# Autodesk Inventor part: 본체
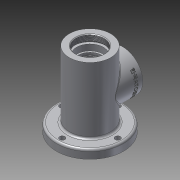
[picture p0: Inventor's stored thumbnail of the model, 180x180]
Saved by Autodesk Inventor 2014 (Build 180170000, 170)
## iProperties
Created: 2016-08
Part Number: 본체
Material: 알루미늄 6061
Document SubType Name: Modeling
Designer: USER
Density: 2.71138 g/cm^3
Appearance: 알루미늄 - 평지
Mass: 767 g
Surface Area: 622.621 cm^2
Volume: 282.882 cm^3
Author: USER
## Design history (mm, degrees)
sketch "스케치3"
  geometry: C1 r 31 at (0, 0); 1 further point
  constraints: 1 centre point, 1 coincident
  dimensions: "d14" = 62 diameter of C1
extrude "돌출1" new body sketch "스케치3" distance "d15" = 115; taper "d16" = 0 deg
node "작업 평면1"
sketch "스케치5"
  geometry: C1 r 50 at (0, 0); 1 further point
  constraints: 1 centre point, 1 coincident
  dimensions: "d19" = 100 diameter of C1
extrude "돌출2" join sketch "스케치5" distance "d20" = 13; taper "d21" = 0 deg
sketch "스케치8"
  geometry: L1 (0, 0)-(0, 115); L2 (0, 0)-(21, 0); L3 (21, 0)-(16, 14); L4 (16, 14)-(12.904, 14); L5 (12.904, 14)-(12.5, 14.7); L6 (12.5, 14.7)-(12.5, 22); L7 (12.5, 22)-(10, 22); L8 (10, 22)-(10, 24.7); L9 (10, 24.7)-(16.5, 24.7); L10 (16.5, 24.7)-(16.5, 29.7); L11 (16.5, 29.7)-(17.5, 29.7); L12 (17.5, 29.7)-(17.5, 38.946); L13 (26, 40)-(26, 78); L14 (26, 78)-(18.262, 78); L15 (17.5, 79.32)-(17.5, 89); L16 (17.5, 89)-(18.5, 89); L17 (18.5, 89)-(18.5, 90.75); L18 (18.5, 90.75)-(17.5, 90.75); L19 (17.5, 90.75)-(17.5, 94); L20 (17.5, 94)-(20, 94); L21 (20, 94)-(20, 103); L22 (20, 103)-(24, 103); L23 (24, 103)-(24, 106); L24 (24, 106)-(21, 106); L25 (21, 106)-(21, 115); L26 (31, 115)-(-31, 115) reference; L27 (26, 59)-(44.925, 59); L28 (21, 115)-(0, 115); L29 (26, 40)-(18.108, 40); L30 (18.108, 40)-(17.5, 38.946); L31 (18.262, 78)-(17.5, 79.32)
  constraints: 60 end point, 14 parallel, 9 perpendicular, 2 midpoint, 1 collinear, 1 point on line, 1 vertical
  dimensions: "d29" = 42 diameter of L2.end L1; "d30" = 32 diameter of L3.end L1; "d31" = 14 vertical distance of L2.end L3.end; "d32" = 25 diameter of L6 L1; "d33" = 7.3 distance of L5.end L6.end; "d34" = 30 deg angle of L6 L5; "d35" = 0.7 vertical distance of L4.end L5.end; "d36" = 20 diameter of L8 L1; "d37" = 2.7 distance of L7.end L8.end; "d38" = 33 diameter of L10 L1; "d40" = 35 diameter of L12 L1; "d42" = 35 diameter of L15 L1; "d43" = 37 diameter of L17 L1; "d44" = 35 diameter of L19 L1; "d45" = 40 diameter of L21 L1; "d46" = 48 diameter of L23 L1; "d47" = 42 diameter of L25 L1; "d48" = 12 vertical distance of L22.end L25.end; "d49" = 3 distance of L22.end L23.end; "d50" = 21 vertical distance of L20.end L25.end; "d51" = 26 vertical distance of L16.end L25.end; "d52" = 1.75 distance of L16.end L17.end; "d56" = 5 distance of L9.end L10.end; "d57" = 56 distance from line of L27.end L26; "d59" = 52 diameter of L13 L1; "d75" = 30 deg angle of L12 L30; "d77" = 38 distance between parallel lines of L29 L14; "d78" = 30 deg angle of L31 L15; "d79" = 1.05391 vertical distance of L29.end L12.end; "d80" = 1.31965 vertical distance of L14.end L15.start
revolve "회전1" sketch "스케치8" stored, may be unused: angle "d60" = 90 deg
feature "스레드1" dims "d61" = 9, "d62" = 0
node "작업 평면5"
sketch "스케치10"
  geometry: L1 (31, 115)-(-31, 115) reference; C1 r 30 at (0, 59); 1 further point
  constraints: 1 centre point, 1 vertical alignment
  dimensions: "d66" = 60 diameter of C1; "d67" = 56 distance from line of C1.centre L1
extrude "돌출3" join sketch "스케치10" stored distance "d68" = 13; taper "d69" = 0 deg
sketch "스케치12"
  geometry: C1 r 30 at (0, 0) reference; C2 r 19 at (0, 0); 1 further point
  constraints: 1 centre point, 1 coincident
  dimensions: "d70" = 38 diameter of C2
extrude "돌출4" cut sketch "스케치12" stored distance "d71" = 13; taper "d72" = 0 deg
fillet "모깎기1" dims "d73" = 3, "d74" = 0.3
sketch "스케치17" dims "d81" = 48
  geometry: C1 r 30 at (0, 0) reference; 3 further points
  constraints: 2 horizontal alignment, 1 coincident, 2 other
hole "구멍2" sketch "스케치17" at (-24, 0) diameter "d82" = 3.242; stored, may be unused: countersink angle "d86" = 90 deg, drill point angle "d88" = 118 deg; dims "d83" = 8, "d84" = 4, "d85" = 2, "d87" = 10
sketch "스케치18" dims "d92" = 83
  geometry: C1 r 31 at (0, 0) reference; C2 r 4 at (41.5, 0); 1 further point
  constraints: 2 horizontal alignment, 1 centre point, 1 coincident, 2 other
  dimensions: "d93" = 8 diameter of C2
extrude "돌출5" cut sketch "스케치18" distance "d94" = 13; taper "d95" = 0 deg
fillet "모깎기2" dims "d99" = 3
node "작업 평면6"
sketch "스케치19"
  geometry: L1 (-18, 56)-(-80, 56) reference; L2 (0, 30)-(0, -30) reference; 2 further points
  constraints: 1 other
  dimensions: "d100" = 56 distance from line of point (-10, 0) L1; "d101" = 10 distance from line of L2 point (-10, 0)
feature "엠보싱1" sketch "스케치19" dims "d102" = 0.5, "d103" = 0
node "작업 평면7"
sketch "스케치20"
  geometry: 1 further point
chamfer "모따기1" distance "d104" = 1; stored, may be unused: second distance "d105" = 2, angle "d106" = 45 deg
chamfer "모따기2" distance "d107" = 1; stored, may be unused: second distance "d108" = 2, angle "d109" = 45 deg
node "솔리드1"
pattern_circular "원형 패턴1" dims angle "d90" = 360 deg
pattern_circular "원형 패턴2" dims angle "d97" = 360 deg
other parameters: "d18" = 3, "d65" = 49
